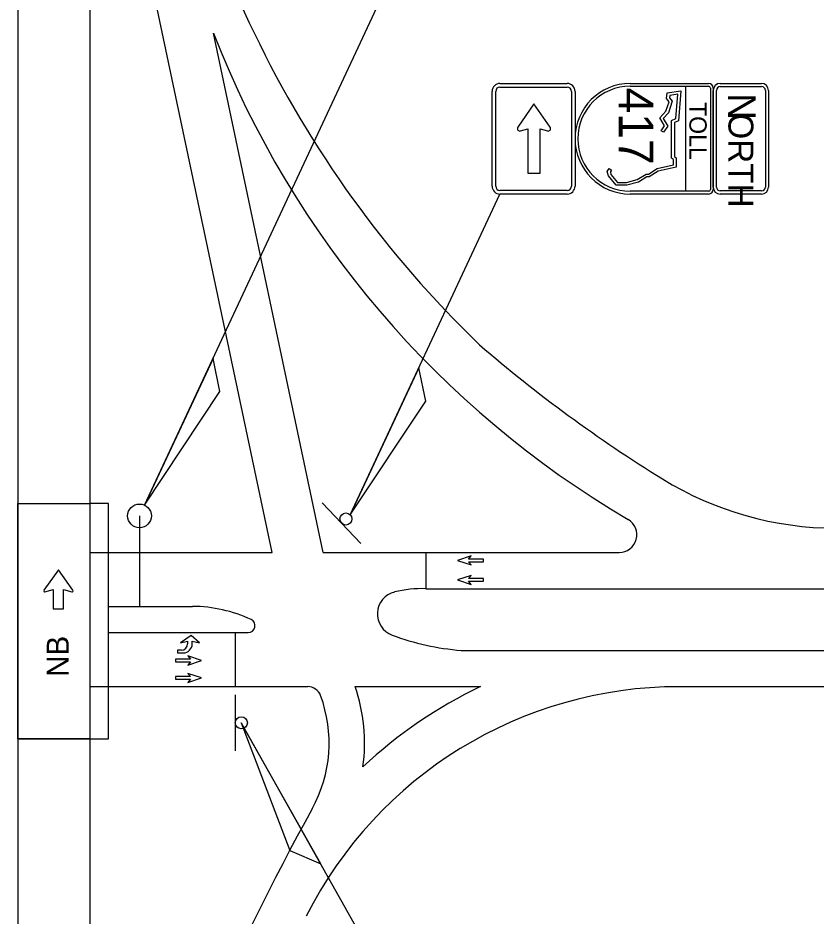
# Model space of a CAD drawing. Extents: x -830008.4 to -829992.7, y 1290284.1 to 1290294.4.
# Drawn here: x -830000.072 to -829997.148, y 1290288.685 to 1290291.974 of the extents above; entities that cross this region are included whole.
import ezdxf

# ---------------------------------------------------------------- set-up
doc = ezdxf.new("R2010")
doc.units = 0
for name, color, linetype in [('DirArrowsPavt', 7, 'Continuous'), ('LeaderLine_dp', 7, 'Continuous'), ('SignPanel', 7, 'Continuous'), ('SignSupport', 7, 'Continuous'), ('SignTruss', 7, 'Continuous'), ('TextLabel', 7, 'Continuous')]:
    doc.layers.add(name, color=color, linetype=linetype)

msp = doc.modelspace()

# ---------------------------------------------------------------- linework, layer by layer
at = {"layer": 'DirArrowsPavt'}
for p, q in [((-829998.4117, 1290290.004), (-829998.4617, 1290289.9873)), ((-829998.4617, 1290289.9873), (-829998.4117, 1290289.9707)), ((-829998.4217, 1290289.9923), (-829998.4117, 1290290.004)), ((-829998.3667, 1290289.9923), (-829998.4217, 1290289.9923)), ((-829998.4117, 1290289.9707), (-829998.4217, 1290289.9823)), ((-829998.4217, 1290289.9823), (-829998.3667, 1290289.9823)), ((-829998.3667, 1290289.9823), (-829998.3667, 1290289.9923)), ((-829998.4117, 1290289.9325), (-829998.4617, 1290289.9159)), ((-829998.4617, 1290289.9159), (-829998.4117, 1290289.8992)), ((-829998.4217, 1290289.9209), (-829998.4117, 1290289.9325)), ((-829998.3667, 1290289.9209), (-829998.4217, 1290289.9209)), ((-829998.3667, 1290289.9109), (-829998.3667, 1290289.9209)), ((-829998.4117, 1290289.8992), (-829998.4217, 1290289.9109)), ((-829998.4217, 1290289.9109), (-829998.3667, 1290289.9109)), ((-829999.4733, 1290289.6587), (-829999.487, 1290289.6587)), ((-829999.4395, 1290289.6258), (-829999.4945, 1290289.6258)), ((-829999.4945, 1290289.6258), (-829999.4945, 1290289.6158)), ((-829999.3995, 1290289.6208), (-829999.4495, 1290289.6374)), ((-829999.4495, 1290289.6374), (-829999.4395, 1290289.6258)), ((-829999.4495, 1290289.6041), (-829999.3995, 1290289.6208)), ((-829999.4945, 1290289.6158), (-829999.4395, 1290289.6158)), ((-829999.4395, 1290289.6158), (-829999.4495, 1290289.6041)), ((-829999.4395, 1290289.5619), (-829999.4945, 1290289.5619)), ((-829999.4945, 1290289.5619), (-829999.4945, 1290289.5519)), ((-829999.3995, 1290289.5569), (-829999.4495, 1290289.5736)), ((-829999.4495, 1290289.5736), (-829999.4395, 1290289.5619)), ((-829999.4495, 1290289.5402), (-829999.3995, 1290289.5569)), ((-829999.4945, 1290289.5519), (-829999.4395, 1290289.5519)), ((-829999.4395, 1290289.5519), (-829999.4495, 1290289.5402))]:
    msp.add_line(p, q, dxfattribs=at)
for points in [[(-829999.4337, 1290289.6815), (-829999.4337, 1290289.6921), (-829999.407, 1290289.6854), (-829999.437, 1290289.7121), (-829999.477, 1290289.6854), (-829999.4504, 1290289.6921), (-829999.4504, 1290289.6817)], [(-829999.487, 1290289.6587), (-829999.487, 1290289.6487), (-829999.4665, 1290289.6487)]]:
    msp.add_lwpolyline(points, dxfattribs=at)
for centre, radius in [((-829999.4733, 1290289.6817), 0.023), ((-829999.4665, 1290289.6815), 0.0328)]:
    msp.add_arc(centre, radius, 270, 0, dxfattribs=at)
at = {"layer": 'LeaderLine_dp'}
for p, q in [((-829999.3574, 1290290.7275), (-829999.6084, 1290290.1898)), ((-829999.3321, 1290290.6066), (-829999.3574, 1290290.7275)), ((-829998.6035, 1290290.6922), (-829998.8545, 1290290.1545)), ((-829998.5782, 1290290.5712), (-829998.6035, 1290290.6922)), ((-829999.6084, 1290290.1898), (-829999.3321, 1290290.6066)), ((-829998.8545, 1290290.1545), (-829998.5782, 1290290.5712)), ((-829999.2537, 1290289.3928), (-829999.0759, 1290288.9255)), ((-829998.9628, 1290288.8756), (-829999.2537, 1290289.3928)), ((-829999.0759, 1290288.9255), (-829998.9628, 1290288.8756))]:
    msp.add_line(p, q, dxfattribs=at)
at = {"layer": 'SignPanel'}
for p, q in [((-829997.6958, 1290291.6787), (-829997.6933, 1290291.6996)), ((-829997.6933, 1290291.6996), (-829997.6432, 1290291.7074)), ((-829997.6548, 1290291.6949), (-829997.6838, 1290291.6904)), ((-829997.6617, 1290291.6055), (-829997.6548, 1290291.6949)), ((-829997.6432, 1290291.7074), (-829997.6517, 1290291.598)), ((-829998.1817, 1290291.6599), (-829998.2409, 1290291.5737)), ((-829998.1224, 1290291.5737), (-829998.1817, 1290291.6599)), ((-829997.6981, 1290291.6326), (-829997.6868, 1290291.6672)), ((-829997.6868, 1290291.6672), (-829997.6958, 1290291.6787)), ((-829997.6751, 1290291.6693), (-829997.6888, 1290291.6271)), ((-829997.6838, 1290291.6904), (-829997.6848, 1290291.6818)), ((-829997.6848, 1290291.6818), (-829997.6751, 1290291.6693)), ((-829997.721, 1290291.6079), (-829997.6981, 1290291.6326)), ((-829997.6888, 1290291.6271), (-829997.708, 1290291.6064)), ((-829997.7039, 1290291.5788), (-829997.721, 1290291.6079)), ((-829997.708, 1290291.6064), (-829997.6915, 1290291.5784)), ((-829997.6779, 1290291.5991), (-829997.6617, 1290291.6055)), ((-829997.6779, 1290291.4609), (-829997.6779, 1290291.5991)), ((-829997.6517, 1290291.598), (-829997.6674, 1290291.5919)), ((-829998.2312, 1290291.5605), (-829998.2044, 1290291.5685)), ((-829998.2044, 1290291.5685), (-829998.2044, 1290291.4061)), ((-829998.1589, 1290291.4061), (-829998.1589, 1290291.5685)), ((-829998.1589, 1290291.5685), (-829998.1321, 1290291.5605)), ((-829997.7157, 1290291.5614), (-829997.7039, 1290291.5788)), ((-829997.7069, 1290291.5555), (-829997.7157, 1290291.5614)), ((-829997.6915, 1290291.5784), (-829997.7069, 1290291.5555)), ((-829997.6674, 1290291.5919), (-829997.6674, 1290291.4665)), ((-829997.671, 1290291.4562), (-829997.6779, 1290291.4609)), ((-829997.6674, 1290291.4665), (-829997.6604, 1290291.4618)), ((-829997.6604, 1290291.4618), (-829997.6604, 1290291.428)), ((-829997.7302, 1290291.4226), (-829997.671, 1290291.4364)), ((-829997.6604, 1290291.428), (-829997.7262, 1290291.4127)), ((-829997.671, 1290291.4364), (-829997.671, 1290291.4562)), ((-829998.2044, 1290291.4061), (-829998.1589, 1290291.4061)), ((-829997.9132, 1290291.4125), (-829997.906, 1290291.4229)), ((-829997.9093, 1290291.3961), (-829997.9132, 1290291.4125)), ((-829997.881, 1290291.3615), (-829997.9093, 1290291.3961)), ((-829997.906, 1290291.4229), (-829997.8973, 1290291.4169)), ((-829997.8973, 1290291.4169), (-829997.9019, 1290291.4104)), ((-829997.9019, 1290291.4104), (-829997.8996, 1290291.4009)), ((-829997.8996, 1290291.4009), (-829997.876, 1290291.3721)), ((-829997.8032, 1290291.3829), (-829997.771, 1290291.4025)), ((-829997.771, 1290291.4025), (-829997.7626, 1290291.4025)), ((-829997.7626, 1290291.4025), (-829997.7302, 1290291.4226)), ((-829997.7262, 1290291.4127), (-829997.7596, 1290291.3919)), ((-829997.876, 1290291.3721), (-829997.8428, 1290291.3721)), ((-829997.8428, 1290291.3721), (-829997.8032, 1290291.3829)), ((-829997.799, 1290291.3731), (-829997.8414, 1290291.3615)), ((-829997.768, 1290291.3919), (-829997.799, 1290291.3731)), ((-829997.7596, 1290291.3919), (-829997.768, 1290291.3919)), ((-829997.8414, 1290291.3615), (-829997.881, 1290291.3615)), ((-829999.9239, 1290289.9526), (-829999.977, 1290289.8779)), ((-829999.8708, 1290289.8779), (-829999.8708, 1290289.8779))]:
    msp.add_line(p, q, dxfattribs=at)
for points in [[(-829998.3062, 1290291.7344), (-829998.0603, 1290291.7344)], [(-829997.8289, 1290291.7344), (-829997.542, 1290291.7344)], [(-829997.8289, 1290291.7243), (-829997.542, 1290291.7243)], [(-829997.6264, 1290291.7243), (-829997.6264, 1290291.3395)], [(-829997.4998, 1290291.7344), (-829997.3479, 1290291.7344)], [(-829998.3351, 1290291.3583), (-829998.3351, 1290291.7055)], [(-829998.3218, 1290291.3583), (-829998.3218, 1290291.7055)], [(-829998.3062, 1290291.7212), (-829998.0603, 1290291.7212)], [(-829998.0446, 1290291.7055), (-829998.0446, 1290291.3583)], [(-829998.0314, 1290291.7055), (-829998.0314, 1290291.3583)], [(-829997.5352, 1290291.7175), (-829997.5352, 1290291.3463)], [(-829997.5251, 1290291.7175), (-829997.5251, 1290291.3463)], [(-829997.5251, 1290291.3547), (-829997.5251, 1290291.7091)], [(-829997.5135, 1290291.3547), (-829997.5135, 1290291.7091)], [(-829997.4998, 1290291.7228), (-829997.3479, 1290291.7228)], [(-829997.3342, 1290291.7091), (-829997.3342, 1290291.3547)], [(-829997.3226, 1290291.7091), (-829997.3226, 1290291.3547)], [(-829998.0603, 1290291.3427), (-829998.3062, 1290291.3427)], [(-829998.0603, 1290291.3294), (-829998.3062, 1290291.3294)], [(-829997.542, 1290291.3395), (-829997.8289, 1290291.3395)], [(-829997.542, 1290291.3294), (-829997.8289, 1290291.3294)], [(-829997.3479, 1290291.341), (-829997.4998, 1290291.341)], [(-829997.3479, 1290291.3294), (-829997.4998, 1290291.3294)], [(-829999.8708, 1290289.8779), (-829999.9239, 1290289.9526), (-829999.9239, 1290289.9526)], [(-829999.9735, 1290289.8721), (-829999.9425, 1290289.8814), (-829999.9425, 1290289.8102), (-829999.9052, 1290289.8102), (-829999.9052, 1290289.8814), (-829999.8743, 1290289.8721)]]:
    msp.add_lwpolyline(points, dxfattribs=at)
for centre, radius, start, end in [((-829998.3062, 1290291.7055), 0.0289, 90, 180), ((-829998.0603, 1290291.7055), 0.0289, 360, 90), ((-829997.8289, 1290291.5319), 0.2025, 90, 270), ((-829997.8289, 1290291.5319), 0.1924, 90, 270), ((-829997.542, 1290291.7175), 0.0169, 0, 90), ((-829997.542, 1290291.7175), 0.00675, 0, 90), ((-829997.4998, 1290291.7091), 0.0253, 90, 180), ((-829997.3479, 1290291.7091), 0.0253, 0, 90), ((-829998.3062, 1290291.7055), 0.0157, 90, 180), ((-829998.0603, 1290291.7055), 0.0157, 360, 89.9456), ((-829997.4998, 1290291.7091), 0.0137, 90, 180), ((-829997.3479, 1290291.7091), 0.0137, 0, 90), ((-829998.2337, 1290291.5688), 0.00868, 145.5119, 286.6443), ((-829998.1296, 1290291.5688), 0.00868, 253.3557, 34.4881), ((-829998.3062, 1290291.3583), 0.0289, 180, 270), ((-829998.3062, 1290291.3583), 0.0157, 180, 270), ((-829998.0603, 1290291.3583), 0.0289, 270, 360), ((-829998.0603, 1290291.3583), 0.0157, 270.0544, 360), ((-829997.542, 1290291.3463), 0.0169, 270, 0), ((-829997.542, 1290291.3463), 0.00675, 270, 0), ((-829997.4998, 1290291.3547), 0.0253, 180, 270), ((-829997.4998, 1290291.3547), 0.0137, 180, 270), ((-829997.3479, 1290291.3547), 0.0253, 270, 0), ((-829997.3479, 1290291.3547), 0.0137, 270, 0), ((-829999.9741, 1290289.8755), 0.00355, 144.6076, 287.1805), ((-829999.8736, 1290289.8755), 0.00355, 252.8195, 35.3924)]:
    msp.add_arc(centre, radius, start, end, dxfattribs=at)
at = {"layer": 'SignSupport'}
for p, q in [((-829998.9574, 1290290.1985), (-829998.8154, 1290290.0495)), ((-829999.2758, 1290289.4957), (-829999.2758, 1290289.2899))]:
    msp.add_line(p, q, dxfattribs=at)
for centre in [(-829998.8704, 1290290.1392), (-829999.2537, 1290289.3928)]:
    msp.add_circle(centre, 0.0221, dxfattribs=at)
at = {"layer": 'SignTruss'}
msp.add_line((-829999.6267, 1290290.1505), (-829999.6267, 1290289.8188), dxfattribs=at)
msp.add_circle((-829999.6267, 1290290.1505), 0.0434, dxfattribs=at)
msp.add_circle((-829999.6267, 1290290.1505), 0.0434, dxfattribs=at)
at = {"layer": 'TextLabel'}
for p, q in [((-830000.0719, 1290294.228), (-830000.0719, 1290285.328)), ((-829999.8091, 1290294.0613), (-829999.8091, 1290288.9868)), ((-829999.1404, 1290290.0166), (-829999.6786, 1290292.5639)), ((-829999.6084, 1290290.1898), (-829998.5302, 1290292.5004)), ((-829998.9542, 1290290.0166), (-829999.356, 1290291.9188)), ((-829998.8545, 1290290.1545), (-829998.3062, 1290291.3294)), ((-830000.0719, 1290290.196), (-829999.8091, 1290290.196)), ((-829999.8091, 1290290.0166), (-829999.1404, 1290290.0166)), ((-829998.9542, 1290290.0166), (-829997.8698, 1290290.0166)), ((-829998.578, 1290290.0166), (-829998.578, 1290289.8838)), ((-829998.578, 1290289.8838), (-829993.659, 1290289.8838)), ((-829999.7401, 1290289.8188), (-829999.4321, 1290289.8188)), ((-829999.7401, 1290289.7229), (-829999.2285, 1290289.7229)), ((-829999.2763, 1290289.7229), (-829999.2763, 1290289.5251)), ((-829998.4483, 1290289.6579), (-829992.7742, 1290289.6579)), ((-829999.8091, 1290289.5251), (-829999.0101, 1290289.5251)), ((-829998.8368, 1290289.5251), (-829998.3772, 1290289.5251)), ((-829997.6499, 1290289.5251), (-829992.7742, 1290289.5251)), ((-829999.2537, 1290289.3928), (-829998.4458, 1290287.9567)), ((-830000.0719, 1290289.3342), (-829999.8091, 1290289.3342)), ((-829999.8091, 1290288.9868), (-829999.8096, 1290286.9607))]:
    msp.add_line(p, q, dxfattribs=at)
msp.add_lwpolyline([(-829999.8091, 1290289.3342), (-830000.0719, 1290289.3342), (-830000.0719, 1290290.196), (-829999.8091, 1290290.196)], close=True, dxfattribs=at)
msp.add_lwpolyline([(-829999.7401, 1290290.196), (-829999.8091, 1290290.196), (-829999.8091, 1290289.3342), (-829999.7401, 1290289.3342), (-829999.7401, 1290290.196)], dxfattribs=at)
for centre, radius, start, end in [((-829995.6233, 1290293.6404), 3.9753, 185.3062, 226.0707), ((-829996.0337, 1290293.2144), 3.566, 201.3035, 239.6251), ((-829994.9707, 1290294.727), 5.2183, 229.1883, 238.3217), ((-829997.0749, 1290291.317), 1.2114, 238.3217, 270), ((-829997.8698, 1290290.0817), 0.0651, 270, 59.6251), ((-829998.5928, 1290289.4737), 0.4104, 87.9263, 104.0818), ((-829998.6725, 1290289.7915), 0.0827, 104.0818, 249.5385), ((-829999.4321, 1290289.3188), 0.5, 64.6242, 90), ((-829999.2285, 1290289.7479), 0.025, 270, 64.6242), ((-829998.3749, 1290290.589), 0.934, 249.5341, 265.495), ((-829997.6499, 1290287.9944), 1.5306, 90, 153.1865), ((-829999.0101, 1290289.4751), 0.05, 20.3256, 90), ((-829999.4321, 1290289.3188), 0.63, 352.0355, 19.1156), ((-829997.6499, 1290287.9944), 1.6947, 115.4166, 133.117), ((-829999.4321, 1290289.3188), 0.5, 331.1587, 20.3256), ((-829990.0742, 1290284.1655), 10.183, 151.15873, 161.43615)]:
    msp.add_arc(centre, radius, start, end, dxfattribs=at)

# ---------------------------------------------------------------- texts
at = {"layer": 'SignPanel'}
for s, height, p in [('417', 0.12656, (-829997.8711, 1290291.7193)), ('TOLL', 0.06328, (-829997.6124, 1290291.6663)), ('N', 0.1013, (-829997.4704, 1290291.6989)), ('ORTH', 0.09113, (-829997.4693, 1290291.625))]:
    msp.add_text(s, height=height, rotation=270, dxfattribs=at).set_placement(p)
at = {"layer": 'TextLabel'}
msp.add_text('NB', height=0.081, rotation=90, dxfattribs=at).set_placement((-829999.8857, 1290289.5607))

doc.saveas('drawing.dxf')
